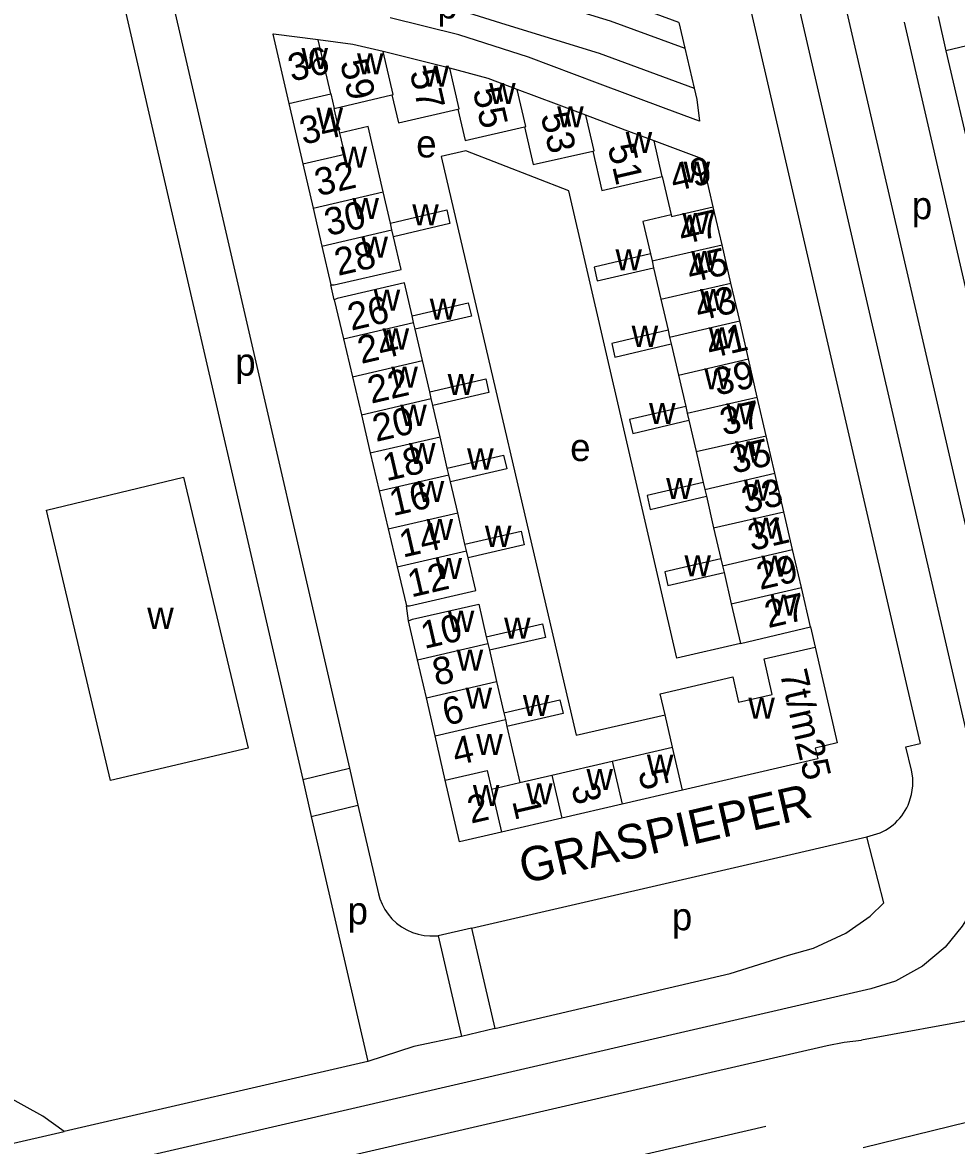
# Model space of a CAD drawing. Extents: x 155696 to 157795, y 382328 to 384028.
# Drawn here: x 156844.2 to 156980.5, y 382975.8 to 383139.6 of the extents above; entities that cross this region are included whole.
import ezdxf

# ---------------------------------------------------------------- set-up
doc = ezdxf.new("R2010")
doc.units = 0
for name, color, linetype in [('BLT_Basislijn', 7, 'Continuous'), ('BLT_Bebouwing', 7, 'Continuous'), ('BLT_Centroide', 7, 'Continuous'), ('BLT_Huisnummer', 7, 'Continuous'), ('BLT_Huisnummer_ tussenligend', 7, 'Continuous'), ('BLT_Huisnummer_reeks', 7, 'Continuous'), ('BLT_Onderverdeling_panden', 7, 'Continuous'), ('BLT_Straatnaam', 7, 'Continuous'), ('BLT_Vlakafsluiter', 7, 'Continuous')]:
    doc.layers.add(name, color=color, linetype=linetype)

msp = doc.modelspace()

# ---------------------------------------------------------------- linework, layer by layer
at = {"layer": 'BLT_Basislijn'}
for p, q in [((156885.14, 383029.19), (156891.94, 383030.84)), ((156891.94, 383030.84), (156893.19, 383025.46)), ((156885.14, 383029.19), (156886.38, 383023.81)), ((156886.38, 383023.81), (156893.19, 383025.46)), ((156956.32, 383018.27), (156967.43, 383020.83)), ((156909.75, 383007.52), (156956.32, 383018.27)), ((156909.75, 383007.52), (156904.87, 383006.41)), ((156904.87, 383006.41), (156908.27, 382991.75)), ((156909.75, 383007.52), (156913.14, 382992.89)), ((156913.14, 382992.89), (156908.27, 382991.75)), ((156908.27, 382991.75), (156901.32, 382990.26)), ((156841.69, 382975.88), (156850.34, 382977.87))]:
    msp.add_line(p, q, dxfattribs=at)
for points in [[(156983.21, 383030.72), (156967.38, 383099.24), (156870.41, 383519.08), (156869.37, 383522.79), (156868.15, 383526.38), (156866.54, 383529.72), (156865.07, 383532.4), (156812.59, 383620.85)], [(156906.38, 383332.24), (156973.29, 383042.58), (156975.17, 383034.43)], [(156878.26, 383152.28), (156894.16, 383150.24), (156905.39, 383147.43), (156916.24, 383144.02), (156929.96, 383139.81), (156940.88, 383135.79)], [(156864.67, 383148.89), (156873.6, 383110.23), (156891.94, 383030.84)], [(156879.46, 383147.09), (156893.23, 383145.32), (156904.03, 383142.61), (156914.76, 383139.25), (156928.36, 383135.07), (156942.22, 383129.97)], [(156846.8, 383145.57), (156858.79, 383143.29), (156862.85, 383125.7), (156885.14, 383029.19)], [(156940.01, 383139.53), (156928.62, 383143.8)], [(156963.72, 383144.42), (156973.83, 383100.67), (156989.57, 383032.51)], [(156907.9, 383137.77), (156897.89, 383140.24)], [(156977.8, 383140.45), (156978.94, 383135.44)], [(156940.01, 383139.53), (156940.88, 383135.79)], [(156972.86, 383139.6), (156984.5, 383089.21)], [(156918.04, 383134.51), (156907.9, 383137.77)], [(156940.88, 383135.79), (156942.22, 383129.97)], [(156928.15, 383130.73), (156918.04, 383134.51)], [(156938.16, 383126.98), (156928.15, 383130.73)], [(156942.22, 383129.97), (156942.6, 383128.32), (156943.01, 383125.16)], [(156943.01, 383125.16), (156938.16, 383126.98)], [(156948.98, 383049.03), (156939.69, 383046.89), (156923.93, 383115.01), (156908.9, 383120.85), (156905.32, 383120.03), (156925, 383035.64), (156937.98, 383038.64)], [(156889.73, 383099.11), (156889.24, 383101.3)], [(156900.55, 383052.32), (156900.25, 383054.52)], [(156959.19, 383051.44), (156959.86, 383048.51)], [(156967.43, 383020.83), (156969.35, 383021.42), (156969.75, 383021.61), (156970.14, 383021.82), (156970.52, 383022.06), (156970.89, 383022.32), (156971.25, 383022.6), (156971.59, 383022.9), (156971.91, 383023.23), (156972.22, 383023.57), (156972.5, 383023.92), (156972.77, 383024.29), (156973.01, 383024.68), (156973.23, 383025.07), (156973.42, 383025.47), (156973.59, 383025.88), (156973.93, 383027.01), (156974.11, 383028.27), (156974.11, 383029.45), (156973.91, 383030.54), (156973.12, 383033.95), (156975.17, 383034.43)], [(156893.19, 383025.46), (156896.17, 383012.55)], [(156886.38, 383023.81), (156894.63, 382988.1)], [(156984.75, 383023.89), (156985.11, 383020.66), (156985.01, 383017.86), (156984.59, 383015.33), (156983.78, 383012.71), (156982.79, 383010.16), (156981.32, 383007.83), (156978.83, 383004.77), (156975.54, 383002), (156971.61, 382999.81), (156968.02, 382998.69)], [(156913.14, 382992.89), (156947.48, 383000.92), (156955.99, 383003.6), (156959.64, 383004.63), (156964.35, 383006.78), (156967.9, 383009.28), (156969.89, 383011.2), (156967.43, 383020.83)], [(156896.17, 383012.55), (156896.39, 383011.79), (156896.7, 383011.02), (156897.09, 383010.27), (156897.58, 383009.55), (156898.15, 383008.87), (156898.81, 383008.26), (156899.53, 383007.72), (156900.31, 383007.26), (156901.13, 383006.9), (156901.98, 383006.63), (156902.83, 383006.46), (156903.68, 383006.39), (156904.87, 383006.41)], [(156968.02, 382998.69), (156832.11, 382967.3), (156696.2, 382935.91)], [(156850.34, 382977.87), (156847.22, 382980.12), (156830.38, 382989.42), (156816.24, 382994.48), (156806.84, 382997.22), (156801.69, 382998.65)], [(156944.08, 382986.39), (156961.62, 382990.44), (156964.11, 382990.91), (156966.63, 382991.18)], [(156901.32, 382990.26), (156894.63, 382988.1)], [(156894.63, 382988.1), (156850.34, 382977.87)], [(156698.21, 382929.18), (156700.55, 382930.03), (156702.94, 382930.69), (156703.41, 382930.8), (156832.52, 382960.62), (156944.08, 382986.39)], [(156685.17, 382918.82), (156697.98, 382919.63), (156716.52, 382922.55), (156790.69, 382939.51), (156849.95, 382954.84), (156952.66, 382978.67)]]:
    msp.add_lwpolyline(points, dxfattribs=at)
at = {"layer": 'BLT_Bebouwing'}
for p, q in [((156936.31, 383103.81), (156937.36, 383099.24)), ((156889.73, 383099.11), (156891.06, 383093.45)), ((156891.06, 383093.45), (156892.37, 383087.91)), ((156938.88, 383092.7), (156939.93, 383088.13)), ((156892.37, 383087.91), (156893.68, 383082.36)), ((156893.68, 383082.36), (156894.99, 383076.82)), ((156941.45, 383081.59), (156942.5, 383077.02)), ((156906.22, 383074.6), (156905.17, 383079.16)), ((156894.99, 383076.82), (156896.3, 383071.28)), ((156942.5, 383077.02), (156943.55, 383072.48)), ((156907.74, 383068.06), (156906.68, 383072.61)), ((156896.3, 383071.28), (156897.61, 383065.73)), ((156944.02, 383070.48), (156945.07, 383065.91)), ((156908.79, 383063.49), (156907.74, 383068.06)), ((156897.61, 383065.73), (156898.91, 383060.18)), ((156945.07, 383065.91), (156946.13, 383061.36)), ((156898.91, 383060.18), (156900.25, 383054.52)), ((156946.59, 383059.37), (156947.64, 383054.8)), ((156912.36, 383048.05), (156913.41, 383043.47)), ((156913.41, 383043.47), (156914.46, 383038.93)), ((156937.98, 383038.64), (156937.28, 383041.7)), ((156939.07, 383033.93), (156937.98, 383038.64)), ((156914.92, 383036.94), (156916.81, 383028.77))]:
    msp.add_line(p, q, dxfattribs=at)
for points in [[(156887.4, 383137.01), (156880.88, 383137.87), (156880.78, 383137.83), (156883.12, 383127.75)], [(156896.87, 383135.32), (156892.42, 383136.35), (156887.4, 383137.01)], [(156982.87, 383118.62), (156990.02, 383120.29), (156986.1, 383137.11), (156978.94, 383135.44)], [(156906.58, 383132.9), (156896.87, 383135.32)], [(156978.94, 383135.44), (156982.87, 383118.62)], [(156916.43, 383129.79), (156912.16, 383131.37), (156906.58, 383132.9)], [(156889.71, 383127.02), (156898.13, 383129)], [(156898.13, 383129), (156899.08, 383124.95), (156907.76, 383126.93)], [(156926.41, 383126.05), (156922.16, 383127.63), (156916.43, 383129.79)], [(156883.12, 383127.75), (156885.16, 383118.93)], [(156890.53, 383123.43), (156889.71, 383127.02)], [(156907.76, 383126.93), (156908.82, 383122.33), (156917.49, 383124.34)], [(156936.38, 383122.32), (156932.18, 383123.87), (156926.41, 383126.05)], [(156896.86, 383114.87), (156894.68, 383124.41), (156890.53, 383123.43)], [(156917.49, 383124.34), (156918.76, 383118.83), (156927.43, 383120.82)], [(156945.01, 383112.69), (156943.39, 383119.68), (156936.38, 383122.32)], [(156927.43, 383120.82), (156928.75, 383115.05), (156937.58, 383117.1)], [(156885.16, 383118.93), (156886.65, 383112.51)], [(156937.58, 383117.1), (156938.87, 383111.5)], [(156897.92, 383110.3), (156896.86, 383114.87)], [(156886.65, 383112.51), (156887.93, 383106.95)], [(156946.3, 383107.14), (156945.01, 383112.69)], [(156897.92, 383110.3), (156906.15, 383112.24), (156906.61, 383110.25), (156898.37, 383108.31)], [(156938.87, 383111.5), (156934.75, 383110.54), (156935.84, 383105.81)], [(156889.24, 383101.3), (156889.7, 383101.32), (156899.47, 383103.56), (156898.37, 383108.31)], [(156887.93, 383106.95), (156889.24, 383101.3)], [(156935.84, 383105.81), (156927.65, 383103.88), (156928.09, 383101.87), (156936.31, 383103.81)], [(156947.59, 383101.54), (156946.3, 383107.14)], [(156901.08, 383096.81), (156899.98, 383101.58), (156890.15, 383099.3), (156889.73, 383099.11)], [(156948.87, 383096.04), (156947.59, 383101.54)], [(156937.36, 383099.24), (156938.42, 383094.69)], [(156901.08, 383096.81), (156909.28, 383098.71), (156909.75, 383096.72), (156901.54, 383094.83)], [(156950.14, 383090.54), (156948.87, 383096.04)], [(156902.6, 383090.27), (156901.54, 383094.83)], [(156938.42, 383094.69), (156930.21, 383092.76), (156930.67, 383090.77), (156938.88, 383092.7)], [(156903.65, 383085.73), (156902.6, 383090.27)], [(156951.43, 383084.95), (156950.14, 383090.54)], [(156939.93, 383088.13), (156940.99, 383083.58)], [(156903.65, 383085.73), (156911.85, 383087.61), (156912.3, 383085.63), (156904.11, 383083.74)], [(156952.74, 383079.31), (156951.43, 383084.95)], [(156905.17, 383079.16), (156904.11, 383083.74)], [(156940.99, 383083.58), (156932.79, 383081.66), (156933.26, 383079.66), (156941.45, 383081.59)], [(156954, 383073.84), (156952.74, 383079.31)], [(156906.22, 383074.6), (156914.42, 383076.48), (156914.88, 383074.49), (156906.68, 383072.61)], [(156955.31, 383068.21), (156954, 383073.84)], [(156943.55, 383072.48), (156935.36, 383070.58), (156935.82, 383068.58), (156944.02, 383070.48)], [(156956.57, 383062.73), (156955.31, 383068.21)], [(156908.79, 383063.49), (156916.99, 383065.39), (156917.45, 383063.41), (156909.25, 383061.52)], [(156957.86, 383057.18), (156956.57, 383062.73)], [(156900.25, 383054.52), (156900.69, 383054.53), (156910.36, 383056.74), (156909.25, 383061.52)], [(156946.13, 383061.36), (156937.93, 383059.46), (156938.4, 383057.46), (156946.59, 383059.37)], [(156959.19, 383051.44), (156957.86, 383057.18)], [(156900.55, 383052.32), (156901.13, 383052.55), (156910.8, 383054.78), (156911.9, 383050.01)], [(156947.64, 383054.8), (156948.98, 383049.03)], [(156901.87, 383046.66), (156900.55, 383052.32)], [(156911.9, 383050.01), (156920.1, 383051.88), (156920.55, 383049.9), (156912.36, 383048.05)], [(156948.98, 383049.03), (156959.19, 383051.44)], [(156959.86, 383048.51), (156963.1, 383034.52), (156959.9, 383033.79), (156960.26, 383032.22), (156940.53, 383027.65)], [(156953.62, 383041.61), (156952.43, 383046.8), (156959.86, 383048.51)], [(156903.16, 383041.1), (156901.87, 383046.66)], [(156937.28, 383041.7), (156947.85, 383044.17)], [(156947.85, 383044.17), (156948.7, 383040.48), (156953.62, 383041.61)], [(156904.44, 383035.55), (156903.16, 383041.1)], [(156914.46, 383038.93), (156922.65, 383040.83), (156923.11, 383038.84), (156914.92, 383036.94)], [(156905.93, 383029.11), (156904.44, 383035.55)], [(156930.28, 383031.89), (156939.07, 383033.93)], [(156921.46, 383029.85), (156930.28, 383031.89)], [(156908.02, 383020.13), (156905.93, 383029.11)], [(156916.81, 383028.77), (156921.46, 383029.85)], [(156940.53, 383027.65), (156931.72, 383025.61)], [(156931.72, 383025.61), (156922.91, 383023.58)], [(156922.91, 383023.58), (156914.1, 383021.54)], [(156914.1, 383021.54), (156908.02, 383020.13)]]:
    msp.add_lwpolyline(points, dxfattribs=at)
msp.add_lwpolyline([(156847.73, 383068.46), (156867.75, 383073.27), (156877.17, 383033.79), (156857.1, 383029.05)], close=True, dxfattribs=at)
at = {"layer": 'BLT_Onderverdeling_panden'}
for p, q in [((156889.21, 383129.16), (156887.4, 383137.01)), ((156883.12, 383127.75), (156889.21, 383129.16)), ((156889.21, 383129.16), (156889.71, 383127.02)), ((156937.58, 383117.1), (156936.38, 383122.32)), ((156886.65, 383112.51), (156896.86, 383114.87)), ((156887.93, 383106.95), (156898.14, 383109.32)), ((156898.14, 383109.32), (156897.92, 383110.3)), ((156935.84, 383105.81), (156936.08, 383104.8)), ((156936.08, 383104.8), (156946.3, 383107.14)), ((156937.36, 383099.24), (156947.59, 383101.54)), ((156901.31, 383095.82), (156901.08, 383096.81)), ((156938.65, 383093.68), (156948.87, 383096.04)), ((156891.06, 383093.45), (156901.31, 383095.82)), ((156901.54, 383094.83), (156901.31, 383095.82)), ((156938.42, 383094.69), (156938.65, 383093.68)), ((156892.37, 383087.91), (156902.6, 383090.27)), ((156939.93, 383088.13), (156950.14, 383090.54)), ((156893.68, 383082.36), (156903.88, 383084.72)), ((156903.88, 383084.72), (156903.65, 383085.73)), ((156904.11, 383083.74), (156903.88, 383084.72)), ((156941.22, 383082.58), (156951.43, 383084.95)), ((156940.99, 383083.58), (156941.22, 383082.58)), ((156894.99, 383076.82), (156905.17, 383079.16)), ((156942.5, 383077.02), (156952.74, 383079.31)), ((156896.3, 383071.28), (156906.45, 383073.61)), ((156943.79, 383071.47), (156954, 383073.84)), ((156945.07, 383065.91), (156955.31, 383068.21)), ((156897.61, 383065.73), (156907.74, 383068.06)), ((156898.91, 383060.18), (156909.02, 383062.51)), ((156946.36, 383060.36), (156956.57, 383062.73)), ((156947.64, 383054.8), (156957.86, 383057.18)), ((156901.87, 383046.66), (156912.13, 383049.03)), ((156903.16, 383041.1), (156913.41, 383043.47)), ((156904.44, 383035.55), (156914.7, 383037.93)), ((156940.53, 383027.65), (156939.07, 383033.93)), ((156930.28, 383031.89), (156931.72, 383025.61)), ((156921.46, 383029.85), (156922.91, 383023.58)), ((156912.65, 383027.8), (156916.81, 383028.77)), ((156912.65, 383027.8), (156914.1, 383021.54))]:
    msp.add_line(p, q, dxfattribs=at)
for points in [[(156898.13, 383129), (156898.32, 383129.05), (156896.87, 383135.32)], [(156907.76, 383126.93), (156907.96, 383126.98), (156906.58, 383132.9)], [(156917.49, 383124.34), (156917.68, 383124.38), (156916.43, 383129.79)], [(156927.43, 383120.82), (156927.63, 383120.86), (156926.41, 383126.05)], [(156885.16, 383118.93), (156891.25, 383120.35), (156890.53, 383123.43)], [(156938.87, 383111.5), (156938.92, 383111.29), (156945.01, 383112.69)], [(156898.37, 383108.31), (156898.14, 383109.32)], [(156936.08, 383104.8), (156936.31, 383103.81)], [(156938.65, 383093.68), (156938.88, 383092.7)], [(156941.22, 383082.58), (156941.45, 383081.59)], [(156906.45, 383073.61), (156906.22, 383074.6)], [(156906.68, 383072.61), (156906.45, 383073.61)], [(156943.55, 383072.48), (156943.79, 383071.47)], [(156943.79, 383071.47), (156944.02, 383070.48)], [(156909.02, 383062.51), (156908.79, 383063.49)], [(156909.25, 383061.52), (156909.02, 383062.51)], [(156946.13, 383061.36), (156946.36, 383060.36)], [(156946.36, 383060.36), (156946.59, 383059.37)], [(156911.9, 383050.01), (156912.13, 383049.03)], [(156912.13, 383049.03), (156912.36, 383048.05)], [(156914.46, 383038.93), (156914.7, 383037.93)], [(156914.7, 383037.93), (156914.92, 383036.94)], [(156905.93, 383029.11), (156912.02, 383030.52), (156912.65, 383027.8)]]:
    msp.add_lwpolyline(points, dxfattribs=at)
at = {"layer": 'BLT_Vlakafsluiter'}
for p, q in [((156997.8, 382996.87), (156966.63, 382991.18)), ((156982.14, 382979.23), (156966.87, 382975.48))]:
    msp.add_line(p, q, dxfattribs=at)

# ---------------------------------------------------------------- texts
at = {"layer": 'BLT_Centroide'}
for s, p in [('p', (156904.77, 383140.14)), ('w', (156884.95, 383132.77)), ('w', (156893.05, 383132)), ('w', (156902.6, 383130.19)), ('w', (156912.32, 383127.66)), ('w', (156887.14, 383124.05)), ('w', (156922.25, 383124.25)), ('e', (156901.68, 383119.88)), ('w', (156932.24, 383120.53)), ('w', (156890.66, 383118.38)), ('w', (156940.69, 383116.19)), ('w', (156892.38, 383110.91)), ('p', (156973.97, 383110.88)), ('w', (156901.11, 383109.98)), ('w', (156940.51, 383108.72)), ('w', (156893.69, 383105.25)), ('w', (156930.75, 383103.42)), ('w', (156941.8, 383103.19)), ('w', (156895.48, 383097.53)), ('w', (156903.66, 383096.21)), ('w', (156943.08, 383097.62)), ('w', (156896.78, 383091.88)), ('w', (156933.11, 383092.27)), ('w', (156944.36, 383092.06)), ('p', (156875.28, 383088.07)), ('w', (156898.06, 383086.31)), ('w', (156906.27, 383085.24)), ('w', (156943.7, 383086.06)), ('w', (156899.35, 383080.75)), ('w', (156935.65, 383081)), ('w', (156946.92, 383080.97)), ('w', (156900.63, 383075.19)), ('e', (156924.14, 383075.62)), ('w', (156948.2, 383075.41)), ('w', (156909.11, 383074.38)), ('w', (156938.14, 383070.09)), ('w', (156901.91, 383069.66)), ('w', (156949.48, 383069.84)), ('w', (156903.2, 383064.09)), ('w', (156950.77, 383064.31)), ('w', (156911.71, 383063.11)), ('w', (156940.81, 383058.82)), ('w', (156952.05, 383058.75)), ('w', (156904.51, 383058.44)), ('w', (156953.36, 383053.09)), ('w', (156862.45, 383051.16)), ('w', (156906.29, 383050.72)), ('w', (156914.5, 383049.72)), ('w', (156907.59, 383045.06)), ('w', (156908.88, 383039.5)), ('w', (156917.24, 383038.46)), ('w', (156950.13, 383038.06)), ('w', (156910.44, 383032.75)), ('w', (156935.33, 383029.75)), ('w', (156926.52, 383027.66)), ('w', (156909.95, 383025.33)), ('w', (156917.71, 383025.59)), ('p', (156891.67, 383008.08)), ('p', (156938.97, 383007.22))]:
    msp.add_text(s, height=4, dxfattribs=at).set_placement(p)
at = {"layer": 'BLT_Huisnummer'}
for s, rotation, p in [('36', 13.0065, (156883.5, 383130.91)), ('59', 283.0087, (156890.56, 383133.76)), ('55', 283.0087, (156909.91, 383129.64)), ('51', 283.0087, (156929.59, 383121.46)), ('32', 13.0065, (156887.38, 383114.21)), ('49', 13.004, (156939.26, 383114.89)), ('28', 13.0065, (156890.27, 383102.6)), ('45', 13.004, (156941.68, 383101.58)), ('26', 13.0065, (156892.2, 383094.61)), ('41', 13.004, (156944.54, 383090.55)), ('22', 13.0065, (156895.11, 383083.97)), ('37', 13.004, (156946.5, 383079.32)), ('35', 13.004, (156947.96, 383073.76)), ('16', 13.0065, (156898.28, 383067.58)), ('31', 13.004, (156950.58, 383062.49)), ('12', 13.0065, (156900.95, 383055.73)), ('27', 13.004, (156953.02, 383051.25)), ('10', 13.0065, (156902.87, 383048.22)), ('6', 13.0065, (156906.02, 383037.02)), ('5', 283.0033, (156934.05, 383030.31)), ('2', 13.0065, (156909.66, 383022.75)), ('1', 283.0029, (156915.67, 383026.06))]:
    msp.add_text(s, height=4, rotation=rotation, dxfattribs=at).set_placement(p)
at = {"layer": 'BLT_Huisnummer_ tussenligend'}
for s, rotation, p in [('57', 283.0087, (156900.72, 383132.32)), ('34', 13.0065, (156885.19, 383121.71)), ('53', 283.0087, (156919.82, 383126.01)), ('30', 13.0065, (156888.81, 383108.4)), ('47', 13.004, (156940.46, 383107.15)), ('43', 13.004, (156942.89, 383096.02)), ('24', 13.0065, (156893.65, 383089.77)), ('39', 13.004, (156945.54, 383085.13)), ('20', 13.0065, (156895.82, 383078.4)), ('18', 13.0065, (156897.32, 383072.66)), ('33', 13.004, (156949.66, 383067.95)), ('14', 13.0065, (156899.73, 383061.53)), ('29', 13.004, (156951.83, 383056.82)), ('8', 13.0065, (156904.58, 383042.83)), ('4', 13.0065, (156907.47, 383031.21)), ('3', 283.0053, (156924.28, 383028.19))]:
    msp.add_text(s, height=4, rotation=rotation, dxfattribs=at).set_placement(p)
at = {"layer": 'BLT_Huisnummer_reeks'}
msp.add_text('7t/m25', height=4, rotation=283.0059, dxfattribs=at).set_placement((156954.7, 383044.76))
at = {"layer": 'BLT_Straatnaam'}
msp.add_text('GRASPIEPER', height=5, rotation=12.995, dxfattribs=at).set_placement((156917.38, 383014))

doc.saveas('drawing.dxf')
